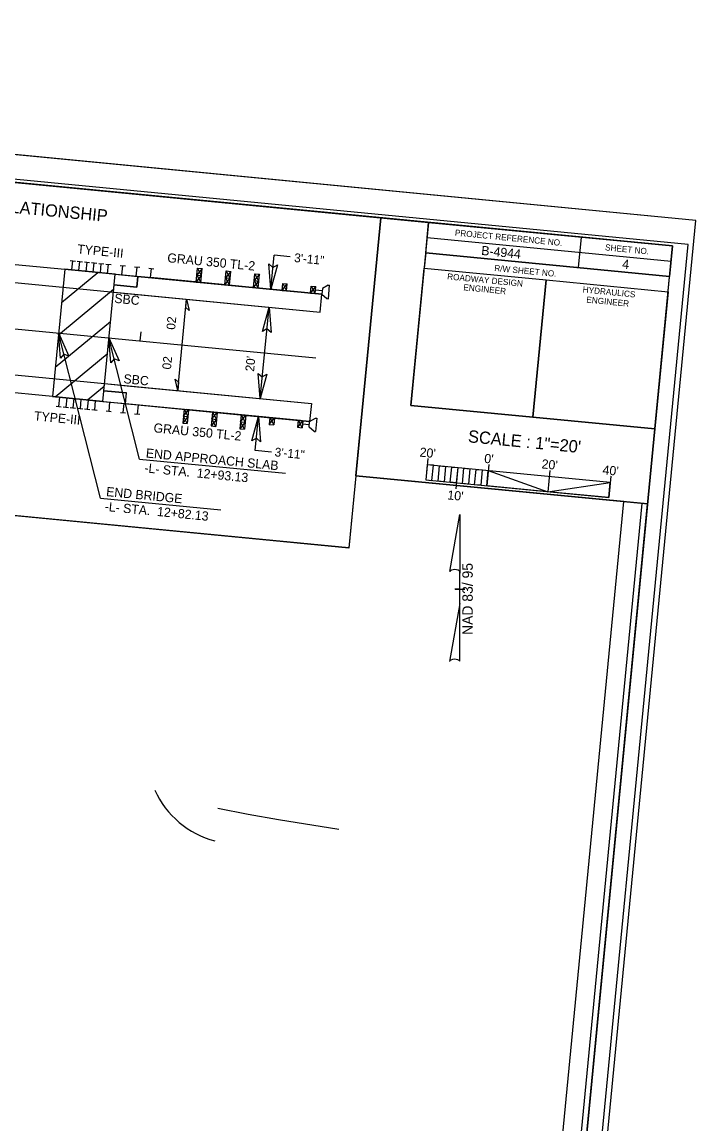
# Model space of a CAD drawing. Extents: x 2060525 to 2062119, y 912110 to 913300.
# Drawn here: x 2061366.5 to 2061586.5, y 912602.5 to 912962.2 of the extents above; entities that cross this region are included whole.
import ezdxf

# ---------------------------------------------------------------- set-up
doc = ezdxf.new("R2010")
doc.units = 0
for name, color, linetype in [('Default', 7, 'Continuous'), ('Prop Approach Slab', 7, 'Continuous'), ('Prop Approach Slab Hatching', 7, 'Continuous'), ('Prop Conc Shoulder Berm Gutter', 7, 'Continuous'), ('Prop DGN Element Guardrail', 7, 'Continuous'), ('Prop Dimension', 7, 'Continuous'), ('Prop Dimension Text', 7, 'Continuous'), ('Prop DSN Text', 7, 'Continuous'), ('Prop EOT', 7, 'Continuous'), ('Prop Guardrail', 7, 'Continuous'), ('Prop Guardrail Anchor Unit CELL', 7, 'Continuous'), ('Prop Horizontal Alignment', 7, 'Continuous'), ('Prop Horizontal Alignment Station Label', 7, 'Continuous'), ('Prop Horizontal Alignment Tick Small', 7, 'Continuous'), ('Prop North Arrow NAD83 for Plan Sheets CELL', 7, 'Continuous'), ('Prop Paved Shoulder', 7, 'Continuous'), ('Prop PHM English Scale CELL', 7, 'Continuous'), ('Prop Roadway Bridge', 7, 'Continuous'), ('Prop Shade Medium', 7, 'Continuous'), ('Prop Structure Anchor Unit CELL', 7, 'Continuous'), ('Prop Superelevation  Arrow CELL', 7, 'Continuous'), ('Prop Superelevation Label', 7, 'Continuous'), ('Prop Terminator CELL', 7, 'Continuous'), ('Scratch_Level_0', 7, 'Continuous'), ('Sheet Clip Boundary CELL', 7, 'Continuous'), ('Sheet Cutting Line CELL', 7, 'Continuous'), ('Sheet Data Field CELL', 7, 'Continuous'), ('Sheet Layout Plan Border', 7, 'Continuous'), ('Sheet Plan CELL', 7, 'Continuous'), ('Sheet Plan Layout CELL', 7, 'Continuous'), ('Sheet Plot Border Inside CELL', 7, 'Continuous'), ('Sheet Plot Border Outside CELL', 7, 'Continuous')]:
    doc.layers.add(name, color=color, linetype=linetype)

msp = doc.modelspace()

# ---------------------------------------------------------------- linework, layer by layer
at = {"layer": 'Prop Approach Slab'}
for p, q in [((2061396.87, 912879.92), (2061380.45, 912881.51)), ((2061392.85, 912838.37), (2061396.87, 912879.92)), ((2061376.43, 912839.95), (2061392.85, 912838.37))]:
    msp.add_line(p, q, dxfattribs=at)
at = {"layer": 'Prop Approach Slab Hatching'}
for p, q in [((2061379.4, 912870.7), (2061391.25, 912880.47)), ((2061378.38, 912860.15), (2061396.39, 912874.98)), ((2061377.36, 912849.59), (2061395.37, 912864.43)), ((2061377.35, 912839.87), (2061394.35, 912853.87)), ((2061387.91, 912838.85), (2061393.33, 912843.31))]:
    msp.add_line(p, q, dxfattribs=at)
at = {"layer": 'Prop Conc Shoulder Berm Gutter'}
for p, q in [((2061396.87, 912879.92), (2061404.33, 912879.2)), ((2061393.19, 912841.85), (2061400.65, 912841.13)), ((2061392.85, 912838.37), (2061400.32, 912837.65))]:
    msp.add_line(p, q, dxfattribs=at)
at = {"layer": 'Prop DGN Element Guardrail'}
for p, q in [((2061380.45, 912881.51), (2061455.1, 912874.3)), ((2061376.43, 912839.95), (2061451.08, 912832.74))]:
    msp.add_line(p, q, dxfattribs=at)
at = {"layer": 'Prop Dimension'}
for p, q in [((2061447.73, 912875.01), (2061448.8, 912886.1)), ((2061454.11, 912885.59), (2061448.8, 912886.1)), ((2061444.28, 912839.3), (2061447.16, 912869.16)), ((2061392.1, 912806.76), (2061378.44, 912860.73)), ((2061404.9, 912819.51), (2061394.86, 912859.15)), ((2061442.64, 912822.36), (2061443.71, 912833.45)), ((2061447.95, 912821.85), (2061442.64, 912822.36)), ((2061404.9, 912819.51), (2061452.49, 912814.91)), ((2061392.1, 912806.76), (2061431.39, 912802.96))]:
    msp.add_line(p, q, dxfattribs=at)
at = {"layer": 'Prop EOT'}
for p, q in [((2061188.02, 912894.21), (2061463.86, 912867.55)), ((2061185.14, 912864.35), (2061460.98, 912837.68))]:
    msp.add_line(p, q, dxfattribs=at)
at = {"layer": 'Prop Guardrail'}
for p, q in [((2061424.16, 912877.29), (2061408.44, 912878.81)), ((2061404.42, 912837.25), (2061413.75, 912836.35))]:
    msp.add_line(p, q, dxfattribs=at)
at = {"layer": 'Prop Guardrail Anchor Unit CELL'}
for p, q in [((2061423.41, 912877.34), (2061423.85, 912881.87)), ((2061425.34, 912881.73), (2061423.63, 912879.61)), ((2061425.12, 912879.46), (2061423.85, 912881.87)), ((2061423.85, 912881.87), (2061425.34, 912881.73)), ((2061424.9, 912877.19), (2061425.34, 912881.73)), ((2061432.74, 912876.44), (2061433.18, 912880.97)), ((2061434.67, 912880.82), (2061432.96, 912878.7)), ((2061434.46, 912878.56), (2061433.18, 912880.97)), ((2061433.18, 912880.97), (2061434.67, 912880.82)), ((2061434.24, 912876.29), (2061434.67, 912880.82)), ((2061442.07, 912875.53), (2061442.51, 912880.07)), ((2061444.01, 912879.92), (2061442.29, 912877.8)), ((2061443.79, 912877.66), (2061442.51, 912880.07)), ((2061442.51, 912880.07), (2061444.01, 912879.92)), ((2061443.57, 912875.39), (2061444.01, 912879.92)), ((2061423.41, 912877.34), (2061425.12, 912879.46)), ((2061423.41, 912877.34), (2061424.9, 912877.19)), ((2061423.63, 912879.61), (2061425.12, 912879.46)), ((2061423.63, 912879.61), (2061424.9, 912877.19)), ((2061461.48, 912873.66), (2061424.16, 912877.27)), ((2061432.74, 912876.44), (2061434.46, 912878.56)), ((2061432.74, 912876.44), (2061434.24, 912876.29)), ((2061432.96, 912878.7), (2061434.46, 912878.56)), ((2061432.96, 912878.7), (2061434.24, 912876.29)), ((2061442.07, 912875.53), (2061443.79, 912877.66)), ((2061442.29, 912877.8), (2061443.79, 912877.66)), ((2061442.29, 912877.8), (2061443.57, 912875.39)), ((2061451.41, 912874.63), (2061451.62, 912876.9)), ((2061451.41, 912874.63), (2061453.12, 912876.75)), ((2061451.62, 912876.9), (2061453.12, 912876.75)), ((2061451.63, 912876.9), (2061452.9, 912874.49)), ((2061452.9, 912874.49), (2061453.12, 912876.75)), ((2061466.48, 912876.33), (2061464.6, 912875.22)), ((2061466.48, 912876.33), (2061466.94, 912876.29)), ((2061466.52, 912871.9), (2061466.94, 912876.29)), ((2061442.07, 912875.53), (2061443.57, 912875.39)), ((2061451.41, 912874.63), (2061452.9, 912874.49)), ((2061460.74, 912873.73), (2061460.96, 912876)), ((2061460.74, 912873.73), (2061462.45, 912875.85)), ((2061460.74, 912873.73), (2061462.23, 912873.59)), ((2061460.96, 912876), (2061462.45, 912875.85)), ((2061460.96, 912876), (2061462.23, 912873.59)), ((2061462.23, 912873.59), (2061462.45, 912875.85)), ((2061462.23, 912873.6), (2061464.43, 912873.39)), ((2061464.53, 912874.47), (2061462.34, 912874.68)), ((2061464.6, 912875.22), (2061464.43, 912873.39)), ((2061464.43, 912873.39), (2061466.06, 912871.94)), ((2061466.06, 912871.94), (2061466.52, 912871.9)), ((2061419.4, 912835.82), (2061418.96, 912831.29)), ((2061420.67, 912833.41), (2061418.96, 912831.29)), ((2061419.18, 912833.55), (2061420.89, 912835.68)), ((2061419.18, 912833.55), (2061420.67, 912833.41)), ((2061420.45, 912831.14), (2061419.18, 912833.55)), ((2061419.4, 912835.82), (2061420.89, 912835.68)), ((2061419.4, 912835.82), (2061420.67, 912833.41)), ((2061457.47, 912832.14), (2061420.14, 912835.75)), ((2061420.89, 912835.68), (2061420.45, 912831.14)), ((2061428.73, 912834.92), (2061428.29, 912830.39)), ((2061428.51, 912832.65), (2061430.22, 912834.77)), ((2061428.73, 912834.92), (2061430.22, 912834.77)), ((2061428.73, 912834.92), (2061430, 912832.51)), ((2061430.22, 912834.77), (2061429.78, 912830.24)), ((2061438.06, 912834.02), (2061437.62, 912829.48)), ((2061437.84, 912831.75), (2061439.55, 912833.87)), ((2061438.06, 912834.02), (2061439.55, 912833.87)), ((2061438.06, 912834.02), (2061439.34, 912831.61)), ((2061439.55, 912833.87), (2061439.12, 912829.34)), ((2061447.39, 912833.11), (2061447.17, 912830.85)), ((2061447.17, 912830.85), (2061448.89, 912832.97)), ((2061447.39, 912833.11), (2061448.89, 912832.97)), ((2061447.39, 912833.11), (2061448.67, 912830.7)), ((2061448.89, 912832.97), (2061448.67, 912830.7)), ((2061418.96, 912831.29), (2061420.45, 912831.14)), ((2061430, 912832.51), (2061428.29, 912830.39)), ((2061428.29, 912830.39), (2061429.78, 912830.24)), ((2061428.51, 912832.65), (2061430, 912832.51)), ((2061429.78, 912830.24), (2061428.51, 912832.65)), ((2061439.34, 912831.61), (2061437.62, 912829.48)), ((2061437.62, 912829.48), (2061439.12, 912829.34)), ((2061437.84, 912831.75), (2061439.34, 912831.61)), ((2061439.12, 912829.34), (2061437.84, 912831.75)), ((2061447.17, 912830.85), (2061448.67, 912830.7)), ((2061456.72, 912832.21), (2061456.5, 912829.95)), ((2061456.5, 912829.95), (2061458, 912829.8)), ((2061456.51, 912829.95), (2061458.22, 912832.07)), ((2061456.72, 912832.21), (2061458.22, 912832.07)), ((2061456.72, 912832.21), (2061458, 912829.8)), ((2061458.22, 912832.07), (2061458, 912829.8)), ((2061460.31, 912830.76), (2061458.11, 912830.98)), ((2061458.22, 912832.05), (2061460.41, 912831.84)), ((2061460.23, 912830.01), (2061460.41, 912831.84)), ((2061461.86, 912828.56), (2061460.23, 912830.01)), ((2061460.41, 912831.84), (2061462.29, 912832.95)), ((2061462.29, 912832.95), (2061462.75, 912832.9)), ((2061462.75, 912832.9), (2061462.32, 912828.52)), ((2061461.86, 912828.56), (2061462.32, 912828.52))]:
    msp.add_line(p, q, dxfattribs=at)
at = {"layer": 'Prop Horizontal Alignment'}
msp.add_line((2061186.58, 912879.28), (2061462.42, 912852.61), dxfattribs=at)
at = {"layer": 'Prop Horizontal Alignment Station Label'}
msp.add_arc((2061437.18, 912723.87), 30, 204.4438, 255.0536, dxfattribs=at)
at = {"layer": 'Prop Horizontal Alignment Tick Small'}
msp.add_line((2061405.12, 912858.15), (2061405.41, 912861.14), dxfattribs=at)
at = {"layer": 'Prop North Arrow NAD83 for Plan Sheets CELL'}
for p, q in [((2061506.16, 912782.9), (2061509.44, 912801.44)), ((2061509.46, 912801.44), (2061509.44, 912801.44)), ((2061509.46, 912801.44), (2061509.44, 912801.44)), ((2061509.46, 912801.44), (2061509.46, 912782.32)), ((2061509.46, 912772.4), (2061509.46, 912782.88)), ((2061509.46, 912782.32), (2061509.46, 912782.86)), ((2061507.86, 912777.04), (2061507.84, 912777.04)), ((2061509.28, 912777.04), (2061507.86, 912777.04)), ((2061507.88, 912777.04), (2061511.08, 912777.04)), ((2061509.46, 912772.4), (2061506.12, 912753.5)), ((2061509.48, 912753.58), (2061509.46, 912772.4))]:
    msp.add_line(p, q, dxfattribs=at)
for centre, start_param, end_param in [((2061507.81, 912782.7), 0.216388, 2.908219), ((2061507.81, 912753.43), 0.201328, 3.141593)]:
    msp.add_ellipse(centre, major_axis=(1.69, -0.01), ratio=0.461098, start_param=start_param, end_param=end_param, dxfattribs=at)
at = {"layer": 'Prop Paved Shoulder'}
for p, q in [((2061396.87, 912879.92), (2061380.45, 912881.51)), ((2061392.85, 912838.37), (2061376.43, 912839.95))]:
    msp.add_line(p, q, dxfattribs=at)
for points in [[(2061396.53, 912876.44), (2061404, 912875.72), (2061404.33, 912879.2), (2061464.43, 912873.41)], [(2061420.14, 912835.72), (2061460.41, 912831.82)]]:
    msp.add_lwpolyline(points, dxfattribs=at)
at = {"layer": 'Prop PHM English Scale CELL'}
for p, q in [((2061499.02, 912819.71), (2061498.34, 912812.74)), ((2061499.06, 912820.11), (2061499.06, 912820.11)), ((2061498.83, 912817.72), (2061498.34, 912812.74)), ((2061558.55, 912811.94), (2061498.83, 912817.72)), ((2061508.78, 912816.76), (2061508.11, 912809.79)), ((2061518.92, 912817.78), (2061518.25, 912810.78)), ((2061538.83, 912815.86), (2061538.16, 912808.89)), ((2061498.34, 912812.74), (2061558.07, 912806.97)), ((2061558.74, 912813.94), (2061558.07, 912806.97)), ((2061558.07, 912806.97), (2061558.55, 912811.94)), ((2061558.78, 912814.33), (2061558.78, 912814.33))]:
    msp.add_line(p, q, dxfattribs=at)
for points in [[(2061500.82, 912817.52), (2061498.83, 912817.72), (2061498.34, 912812.74), (2061500.33, 912812.55)], [(2061502.81, 912817.33), (2061504.8, 912817.14), (2061504.32, 912812.16), (2061502.33, 912812.36)], [(2061506.79, 912816.95), (2061508.78, 912816.76), (2061508.3, 912811.78), (2061506.31, 912811.97)], [(2061510.77, 912816.56), (2061512.76, 912816.37), (2061512.28, 912811.39), (2061510.29, 912811.59)], [(2061514.75, 912816.18), (2061516.74, 912815.99), (2061516.26, 912811.01), (2061514.27, 912811.2)], [(2061518.73, 912815.79), (2061538.16, 912808.89), (2061518.25, 912810.82)], [(2061538.16, 912808.89), (2061558.55, 912811.94), (2061558.07, 912806.97)]]:
    msp.add_lwpolyline(points, close=True, dxfattribs=at)
at = {"layer": 'Prop Roadway Bridge'}
for p, q in [((2061272.57, 912891.94), (2061380.45, 912881.51)), ((2061380.45, 912881.51), (2061376.43, 912839.95)), ((2061376.43, 912839.95), (2061268.56, 912850.38))]:
    msp.add_line(p, q, dxfattribs=at)
at = {"layer": 'Prop Shade Medium'}
for points in [[(2061404.33, 912879.2), (2061404, 912875.72), (2061396.53, 912876.44), (2061396.3, 912874.08), (2061463.86, 912867.55), (2061464.43, 912873.39)], [(2061460.41, 912831.82), (2061400.31, 912837.62), (2061400.65, 912841.13), (2061393.19, 912841.85), (2061393.42, 912844.22), (2061400.88, 912843.49), (2061460.98, 912837.68)]]:
    msp.add_lwpolyline(points, close=True, dxfattribs=at)
at = {"layer": 'Prop Structure Anchor Unit CELL'}
for p, q in [((2061382.21, 912884.35), (2061383.92, 912884.19)), ((2061382.78, 912881.29), (2061383.07, 912884.27)), ((2061384.54, 912884.13), (2061386.25, 912883.96)), ((2061385.11, 912881.06), (2061385.4, 912884.05)), ((2061386.88, 912883.9), (2061388.59, 912883.74)), ((2061387.44, 912880.83), (2061387.73, 912883.82)), ((2061389.21, 912883.68), (2061390.92, 912883.51)), ((2061389.78, 912880.61), (2061390.07, 912883.6)), ((2061391.54, 912883.45), (2061393.25, 912883.29)), ((2061392.11, 912880.38), (2061392.4, 912883.37)), ((2061380.45, 912881.51), (2061408.44, 912878.81)), ((2061393.88, 912883.23), (2061395.59, 912883.06)), ((2061394.44, 912880.16), (2061394.73, 912883.14)), ((2061398.54, 912882.78), (2061400.25, 912882.61)), ((2061399.11, 912879.71), (2061399.4, 912882.69)), ((2061403.21, 912882.32), (2061404.92, 912882.16)), ((2061403.77, 912879.26), (2061404.06, 912882.24)), ((2061407.87, 912881.87), (2061409.58, 912881.71)), ((2061408.44, 912878.81), (2061408.73, 912881.79)), ((2061376.43, 912839.95), (2061404.42, 912837.25)), ((2061377.62, 912836.83), (2061379.33, 912836.66)), ((2061378.76, 912839.73), (2061378.47, 912836.74)), ((2061379.95, 912836.6), (2061381.66, 912836.44)), ((2061381.09, 912839.5), (2061380.81, 912836.52)), ((2061383.43, 912839.28), (2061383.14, 912836.29)), ((2061385.76, 912839.05), (2061385.47, 912836.07)), ((2061388.09, 912838.83), (2061387.8, 912835.84)), ((2061390.43, 912838.6), (2061390.14, 912835.62)), ((2061395.09, 912838.15), (2061394.8, 912835.16)), ((2061399.76, 912837.7), (2061399.47, 912834.71)), ((2061404.42, 912837.25), (2061404.13, 912834.26)), ((2061382.28, 912836.38), (2061383.99, 912836.21)), ((2061384.62, 912836.15), (2061386.33, 912835.98)), ((2061386.95, 912835.92), (2061388.66, 912835.76)), ((2061389.28, 912835.7), (2061390.99, 912835.53)), ((2061393.95, 912835.25), (2061395.66, 912835.08)), ((2061398.61, 912834.8), (2061400.32, 912834.63)), ((2061403.28, 912834.35), (2061404.99, 912834.18))]:
    msp.add_line(p, q, dxfattribs=at)
at = {"layer": 'Prop Superelevation  Arrow CELL'}
msp.add_line((2061417.36, 912841.9), (2061420.25, 912871.76), dxfattribs=at)
for points in [[(2061420.25, 912871.76), (2061421.1, 912868.06), (2061419.98, 912869)], [(2061417.36, 912841.9), (2061416.51, 912845.6), (2061417.63, 912844.66)]]:
    msp.add_lwpolyline(points, close=True, dxfattribs=at)
at = {"layer": 'Prop Terminator CELL'}
for points in [[(2061449.9, 912882.94), (2061447.73, 912875.01), (2061447.08, 912883.25), (2061448.41, 912882.08)], [(2061445, 912861.23), (2061447.16, 912869.16), (2061447.81, 912860.91), (2061446.48, 912862.08)], [(2061379.07, 912852.54), (2061378.44, 912860.73), (2061381.83, 912853.19), (2061380.18, 912853.84)], [(2061395.5, 912850.95), (2061394.86, 912859.15), (2061398.26, 912851.6), (2061396.61, 912852.25)], [(2061446.45, 912847.23), (2061444.28, 912839.3), (2061443.63, 912847.54), (2061444.96, 912846.38)], [(2061441.54, 912825.52), (2061443.71, 912833.45), (2061444.36, 912825.21), (2061443.03, 912826.37)]]:
    msp.add_lwpolyline(points, close=True, dxfattribs=at)
at = {"layer": 'Scratch_Level_0'}
for p, q in [((2061440.32, 912703.5), (2061430.46, 912705.46)), ((2061450.2, 912701.79), (2061440.32, 912703.5)), ((2061469.99, 912698.66), (2061450.2, 912701.79))]:
    msp.add_line(p, q, dxfattribs=at)
at = {"layer": 'Sheet Clip Boundary CELL'}
msp.add_lwpolyline([(2060947.75, 912528.18), (2061534.24, 912471.49), (2061175.38, 912506.18), (2061182.37, 912578.54), (2061543.72, 912543.62), (2061569, 912805.1), (2061475.51, 912814.14), (2061473.23, 912790.55), (2061159.65, 912820.86), (2061167, 912896.82), (2061010.06, 912911.99), (2061013.14, 912943.82), (2060988.16, 912946.23)], close=True, dxfattribs=at)
at = {"layer": 'Sheet Cutting Line CELL'}
msp.add_line((2061586.54, 912897.43), (2060916.27, 912962.22), dxfattribs=at)
at = {"layer": 'Sheet Layout Plan Border'}
msp.add_lwpolyline([(2060947.75, 912528.18), (2061530.76, 912471.83), (2061563.03, 912805.68), (2061475.51, 912814.14), (2061483.65, 912898.34), (2060988.16, 912946.23)], close=True, dxfattribs=at)
at = {"layer": 'Sheet Plan CELL'}
for p, q in [((2061498.77, 912891.84), (2061578.42, 912884.13)), ((2061549.03, 912891.99), (2061548.09, 912882.04)), ((2061498.3, 912886.85), (2061497.82, 912881.87)), ((2061498.3, 912886.85), (2061577.94, 912879.16)), ((2061498.3, 912886.85), (2061577.94, 912879.16)), ((2061537.65, 912878.02), (2061533.33, 912833.25))]:
    msp.add_line(p, q, dxfattribs=at)
for points in [[(2061578.92, 912889.13), (2060981.69, 912946.86), (2060941.28, 912528.81), (2061538.5, 912471.08)], [(2060941.28, 912528.81), (2060981.68, 912946.85), (2061499.26, 912896.83), (2061493.49, 912837.09), (2061573.14, 912829.38), (2061538.5, 912471.08)], [(2061170.06, 912928.65), (2061483.65, 912898.34), (2061473.22, 912790.47), (2061159.65, 912820.86)], [(2061499.26, 912896.83), (2061578.92, 912889.13), (2061577.94, 912879.16), (2061498.3, 912886.85)], [(2061497.82, 912881.87), (2061537.65, 912878.02), (2061533.32, 912833.23), (2061493.49, 912837.09)], [(2061537.65, 912878.02), (2061577.46, 912874.18), (2061573.14, 912829.38), (2061533.32, 912833.23)]]:
    msp.add_lwpolyline(points, close=True, dxfattribs=at)
at = {"layer": 'Sheet Plan Layout CELL'}
for points in [[(2060981.68, 912946.85), (2060941.28, 912528.81), (2061538.5, 912471.08), (2061570.77, 912804.93), (2061475.51, 912814.14), (2061483.65, 912898.34)], [(2061475.51, 912814.14), (2061570.78, 912804.93), (2061578.93, 912889.13), (2061483.65, 912898.34)]]:
    msp.add_lwpolyline(points, close=True, dxfattribs=at)
at = {"layer": 'Sheet Plot Border Inside CELL'}
msp.add_lwpolyline([(2060880.07, 912533.71), (2061543.38, 912469.6), (2061583.98, 912889.64), (2060920.68, 912953.76)], close=True, dxfattribs=at)
at = {"layer": 'Sheet Plot Border Outside CELL'}
msp.add_lwpolyline([(2060874.13, 912526.25), (2061544.4, 912461.46), (2061586.54, 912897.43), (2060916.27, 912962.22)], close=True, dxfattribs=at)

# ---------------------------------------------------------------- texts
at = {"layer": 'Default'}
for p in [(2061396.54, 912870.6), (2061399.53, 912844.35)]:
    msp.add_text('SBC', height=3, rotation=354.4787, dxfattribs=at).set_placement(p)
at = {"layer": 'Prop Dimension Text'}
for s, height, rotation, p in [('3\'-11"', 2.88, 354.4787, (2061455.26, 912883.89)), ("20'", 2.88, 84.4787, (2061442.25, 912848.02)), ('END APPROACH SLAB', 3, 354.4787, (2061406.84, 912820.08)), ('3\'-11"', 2.88, 354.4787, (2061448.89, 912820.46)), ('-L- STA.  12+93.13', 3, 354.4787, (2061406.37, 912815.23)), ('END BRIDGE', 3, 354.4787, (2061393.88, 912807.5)), ('-L- STA.  12+82.13', 3, 354.4787, (2061393.41, 912802.65))]:
    msp.add_text(s, height=height, rotation=rotation, dxfattribs=at).set_placement(p)
at = {"layer": 'Prop DSN Text'}
msp.add_text('SCALE : 1"=20\'', height=4, rotation=354.4787, dxfattribs=at).set_placement((2061511.99, 912825.07))
at = {"layer": 'Prop Guardrail Anchor Unit CELL'}
for p in [(2061413.84, 912883.83), (2061409.35, 912828.32)]:
    msp.add_text('GRAU 350 TL-2', height=3, rotation=354.4787, dxfattribs=at).set_placement(p)
at = {"layer": 'Prop Horizontal Alignment Station Label'}
msp.add_text('SKETCH SHOWING BRIDGE & PAVEMENT RELATIONSHIP', height=4, rotation=354.4787, dxfattribs=at).set_placement((2061246.96, 912911.19))
at = {"layer": 'Prop North Arrow NAD83 for Plan Sheets CELL'}
msp.add_text('NAD 83/ 95', height=3.4, rotation=90, dxfattribs=at).set_placement((2061513.67, 912762.14))
at = {"layer": 'Prop PHM English Scale CELL'}
for s, p in [("20'", (2061496.22, 912820.38)), ("0'", (2061517.31, 912818.34)), ("20'", (2061536.04, 912816.53)), ("40'", (2061555.94, 912814.61)), ("10'", (2061505.28, 912806.41))]:
    msp.add_text(s, height=3, rotation=354.4787, dxfattribs=at).set_placement(p)
at = {"layer": 'Prop Structure Anchor Unit CELL'}
for p in [(2061384.41, 912886.69), (2061370.33, 912832.22)]:
    msp.add_text('TYPE-III', height=3, rotation=354.4787, dxfattribs=at).set_placement(p)
at = {"layer": 'Prop Superelevation Label'}
for p in [(2061416.48, 912861.68), (2061415.12, 912848.71)]:
    msp.add_text('02', height=2.88, rotation=84.4787, dxfattribs=at).set_placement(p)
at = {"layer": 'Sheet Data Field CELL'}
for s, p in [('B-4944', (2061516.35, 912886.21)), ('4', (2061562.35, 912881.79))]:
    msp.add_text(s, height=3, rotation=354.4787, dxfattribs=at).set_placement(p)
at = {"layer": 'Sheet Plan CELL'}
for s, p in [('PROJECT REFERENCE NO.', (2061507.77, 912892.51)), ('SHEET NO.', (2061556.8, 912887.72)), ('ROADWAY DESIGN', (2061505.25, 912878.22)), ('R/W SHEET NO.', (2061520.64, 912880.99)), ('ENGINEER', (2061510.53, 912874.68)), ('HYDRAULICS', (2061549.5, 912873.95)), ('ENGINEER', (2061550.69, 912870.64))]:
    msp.add_text(s, height=2, rotation=354.4787, dxfattribs=at).set_placement(p)

doc.saveas('drawing.dxf')
